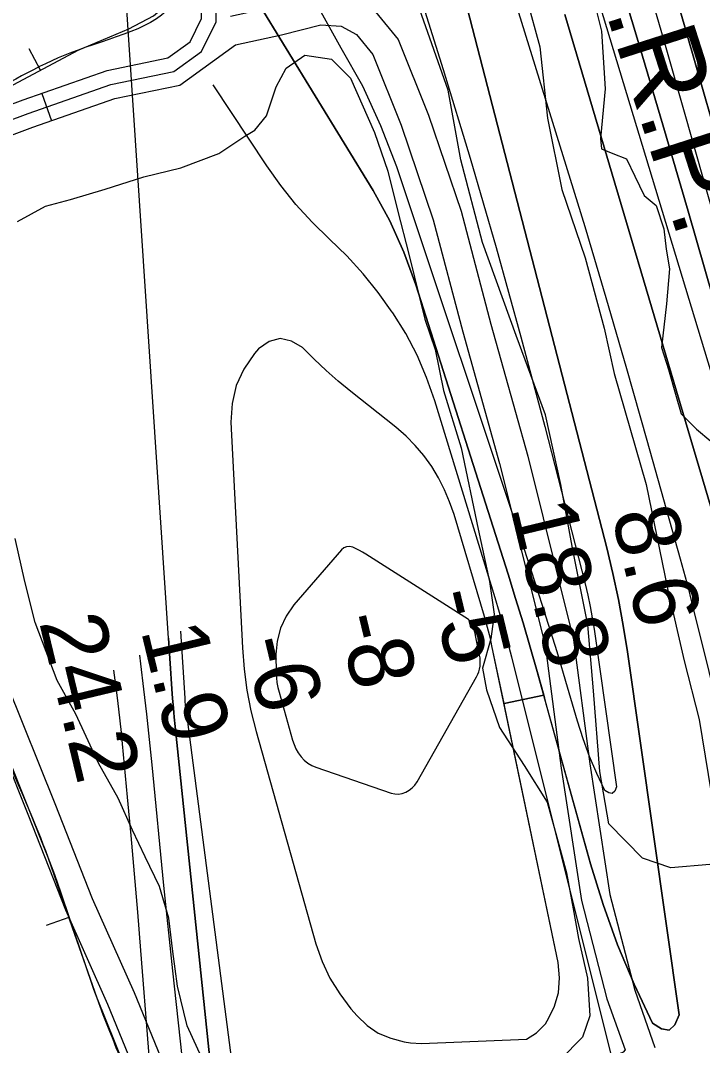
# Model space of a CAD drawing. Extents: x 3625074 to 3663148, y 511451 to 537151.
# Drawn here: x 3631335 to 3632039, y 525814 to 526871 of the extents above; entities that cross this region are included whole.
import ezdxf

# ---------------------------------------------------------------- set-up
doc = ezdxf.new("R2010")
doc.units = 0
for name, color, linetype in [('V-BORW-LINE', 7, 'Continuous'), ('V-RIVR-EDGE', 7, 'Continuous'), ('V-RIVR-RANG', 7, 'Continuous'), ('V-ROAD-CNTR', 7, 'Continuous'), ('V-SITE-VEGE', 7, 'Continuous'), ('V-TOPO-DPTH', 7, 'Continuous'), ('V-TOPO-MINR', 7, 'Continuous'), ('V-TOPO-WATR', 7, 'Continuous'), ('V-TOPO-WATR-IDEN', 7, 'Continuous')]:
    doc.layers.add(name, color=color, linetype=linetype)

msp = doc.modelspace()

# ---------------------------------------------------------------- linework, layer by layer
at = {"layer": 'V-BORW-LINE'}
for p, q in [((3631356.1, 526819.9), (3631344.3, 526841.9)), ((3631385.4, 525946.2), (3631361.8, 525938))]:
    msp.add_line(p, q, dxfattribs=at)
for points in [[(3631302.6, 526791.3), (3631394.9, 526840.7), (3631447.3, 526862.6), (3631472.7, 526875.8), (3631495.6, 526895.8), (3631500.9, 526904.6), (3631502.9, 526912.6), (3631502, 526927.5), (3631488.9, 526973.4), (3631483.9, 527016), (3631478.3, 527058.7), (3631470.8, 527099.7), (3631466.8, 527113.2)], [(3631566.8, 526751.7), (3631577.2, 526758.1), (3631589.1, 526772.9), (3631599.1, 526802.6), (3631609.6, 526822), (3631628.6, 526835.4), (3631656.4, 526831.3), (3631675.7, 526811.6), (3631700.5, 526755.6), (3631714.4, 526715.9), (3631724.3, 526675.6), (3631736.2, 526628.7), (3631752.5, 526563.1), (3631763.2, 526531.8), (3631771.9, 526489.6), (3631790.1, 526430.4), (3631807.4, 526346.5), (3631819.2, 526292.5), (3631824.1, 526258.8), (3631820.6, 526233.5), (3631811.9, 526203.1), (3631816.2, 526181), (3631829.5, 526141.9), (3631855, 526102.8), (3631878.7, 526064.9), (3631888.7, 526029.1), (3631898.7, 525992.1), (3631905.5, 525955), (3631911, 525924.5), (3631920.4, 525883.5), (3631922.6, 525844.6), (3631915.2, 525822.6), (3631892.3, 525799.5)], [(3631332.4, 526663.8), (3631361.1, 526679.7), (3631387.1, 526686.6), (3631422.9, 526697.3), (3631462.6, 526709.9), (3631501, 526719.2), (3631540, 526733.8), (3631566.8, 526751.7)], [(3631441.8, 525795.7), (3631414.5, 525862.8), (3631389.1, 525935.4), (3631364.1, 526008.1), (3631321.4, 526115), (3631278, 526221.5), (3631246.4, 526324.2), (3631214.4, 526427.2), (3631196.1, 526467.4), (3631126.7, 526580.9), (3631116.6, 526597.1), (3631110.5, 526604.2), (3631102.9, 526609.5), (3631096.8, 526611.7), (3631085.7, 526612.6), (3631068.7, 526609.7), (3631052, 526605.2), (3631013.3, 526596.3), (3630975, 526585.1)], [(3631527.6, 525790), (3631507.3, 525834.3), (3631497.3, 525875.3), (3631492.5, 525911), (3631488.3, 525945.4), (3631478.9, 525978), (3631464.2, 526008.6), (3631450.9, 526036), (3631436.3, 526069.2), (3631415.9, 526105.1), (3631392.4, 526155.9), (3631373.2, 526190.5), (3631350.5, 526250.4), (3631339.8, 526292.6), (3631329.9, 526336.9)]]:
    msp.add_lwpolyline(points, dxfattribs=at)
for points in [[(3631461.6, 527110), (3631478.3, 527058.7), (3631488.9, 526973.4), (3631495.6, 526895.8), (3631394.9, 526840.7), (3631210, 526742.4), (3630952, 526645.6), (3630828.4, 526574.9), (3630771.3, 526644.6), (3630731.1, 526688.9), (3630681.2, 526790.4), (3630607.6, 526957.1), (3630583.6, 527107), (3630755.8, 527189), (3630946.7, 527280.8), (3631080.7, 527338.8)], [(3630975, 526585.1), (3631052, 526605.2), (3631102.9, 526609.5), (3631126.7, 526580.9), (3631214.4, 526427.2), (3631278, 526221.5), (3631364.1, 526008.1), (3631414.5, 525862.8), (3631469.9, 525728.9), (3631500, 525646), (3631501, 525593.6), (3631358.1, 525555.8), (3631253.3, 525516), (3631197.2, 525519.2), (3631149.8, 525621.4), (3631070.3, 525800.1), (3631011.3, 525959), (3630940.1, 526137.7), (3630858.5, 526350.5), (3630820.7, 526446.1), (3630877.9, 526518.8), (3630942, 526565.5), (3630975, 526585.1)]]:
    msp.add_spline(points, degree=3, dxfattribs=at)
at = {"layer": 'V-RIVR-EDGE'}
msp.add_lwpolyline([(3631925.1, 526899.1), (3631934.6, 526860.1), (3631938.7, 526800.7), (3631933.7, 526749.6), (3631934.9, 526738.8), (3631946.3, 526734), (3631960.7, 526728.6), (3631969.1, 526710.5), (3631978.6, 526690.7), (3631991.2, 526680.5), (3631998.9, 526656.4), (3632001.3, 526635.4), (3632004.8, 526615), (3632001.7, 526579), (3631996.8, 526534), (3632004, 526511.1), (3632011.1, 526485.9), (3632017.1, 526465.5), (3632032.6, 526449.8), (3632047.6, 526437.2)], dxfattribs=at)
at = {"layer": 'V-ROAD-CNTR'}
msp.add_line((3631357.4, 526796), (3631367.3, 526767.6), dxfattribs=at)
for points in [[(3630816, 526562.2), (3630852.9, 526576.9), (3631064.9, 526672), (3631118.7, 526691), (3631165.4, 526724.2), (3631214.2, 526743.2), (3631338.2, 526789.2), (3631424.8, 526819.5), (3631487.5, 526832.5), (3631510.5, 526849.1), (3631522.2, 526873.3), (3631522, 526911.9), (3631512.6, 526969.7), (3631503.7, 527024.9), (3631476.8, 527089), (3631432.3, 527198.3), (3631386.5, 527303.3), (3631345.3, 527392), (3631339.9, 527430.9), (3631344.3, 527503), (3631470.3, 527554.5), (3631540.1, 527549.8), (3631599.2, 527529.4)], [(3631219.5, 526729.1), (3631343.3, 526775.1), (3631428.8, 526805.1), (3631493.6, 526818.5), (3631522.3, 526839.1), (3631537.2, 526869.9), (3631537, 526913.2), (3631527.4, 526972.2), (3631518.2, 527029), (3631490.6, 527094.8), (3631446.1, 527204.2), (3631400.1, 527309.5), (3631359.8, 527396.3), (3631354.9, 527431.5), (3631358.7, 527492.7), (3631472.8, 527539.3), (3631537.1, 527534.9), (3631594.3, 527515.3)], [(3631552.2, 526875.5), (3631597.7, 526885.5), (3631642.4, 526897), (3631675, 526894.7), (3631701.5, 526880.1), (3631725, 526851.4), (3631756.3, 526773.5), (3631789.9, 526674.4), (3631820.7, 526557.8), (3631858.6, 526421.8), (3631906, 526232.6), (3631922.8, 526104.5), (3631943.4, 525969.7), (3631969, 525871.2), (3631989.9, 525812.1)], [(3631557.3, 526845.9), (3631604.7, 526856.3), (3631645.1, 526866.8), (3631666.3, 526865.3), (3631682, 526856.6), (3631698.9, 526836), (3631728.1, 526763.1), (3631761.2, 526665.7), (3631791.8, 526549.9), (3631829.6, 526414.2), (3631876.5, 526227), (3631893.1, 526100.2), (3631914, 525963.6), (3631940.3, 525862.4), (3631959.1, 525809.5), (3631957.1, 525807.2), (3631893, 525778.3), (3631760.8, 525723.5), (3631659.9, 525686.7), (3631599.1, 525675.4), (3631553.6, 525672.7), (3631537.8, 525673.8)], [(3631133.3, 526664.5), (3631179.8, 526697.6), (3631224.9, 526715.1), (3631348.3, 526761), (3631432.8, 526790.6), (3631499.8, 526804.4), (3631557.3, 526845.9)], [(3631133.3, 526664.5), (3631163.9, 526617), (3631186.3, 526573.3), (3631204.4, 526526.6), (3631229.7, 526446.2), (3631256.1, 526368.3), (3631288.2, 526275.4), (3631321.6, 526186), (3631371, 526063.6), (3631409.5, 525965.6), (3631452.6, 525868.6), (3631486.2, 525787.3), (3631521.7, 525710.5), (3631537.8, 525673.8)], [(3631104.3, 526654.1), (3631137.9, 526602), (3631158.9, 526561), (3631176.1, 526516.6), (3631201.2, 526436.9), (3631227.8, 526358.6), (3631260, 526265.3), (3631293.7, 526175.1), (3631343.1, 526052.5), (3631381.8, 525954), (3631425.1, 525856.8), (3631458.7, 525775.3), (3631494.3, 525698.2), (3631513.5, 525654.5), (3631518.5, 525634.7), (3631523, 525587.2), (3631523.3, 525553.5)]]:
    msp.add_lwpolyline(points, dxfattribs=at)
at = {"layer": 'V-SITE-VEGE'}
for points in [[(3631857.6, 526893.1), (3631871, 526844), (3631879.2, 526770.5), (3631894, 526696.9), (3631917.8, 526626.5), (3631937.5, 526553.7), (3631947.7, 526507), (3631980.8, 526392.5), (3632002.7, 526285.3), (3632019.9, 526210.9), (3632035.6, 526150.3), (3632054.1, 526036.7)], [(3632046.4, 526000.9), (3632006.4, 525997.2), (3631977.1, 526007.3), (3631942.4, 526042.7), (3631933.1, 526096.7), (3631926.6, 526180), (3631920.7, 526247.8), (3631905.1, 526325.4), (3631892.7, 526392.5), (3631877.1, 526464.5), (3631846.8, 526546.4), (3631811.9, 526642.2), (3631789.8, 526727.3), (3631776.7, 526799.2), (3631747.3, 526882)]]:
    msp.add_lwpolyline(points, dxfattribs=at)
at = {"layer": 'V-TOPO-DPTH'}
for points in [[(3631686.1, 527974.3), (3631902.6, 527272.7), (3631906.4, 527260.2), (3631910.3, 527247.6), (3631914.1, 527235.1), (3631917.8, 527222.5), (3631921.5, 527209.9), (3631925.2, 527197.4), (3631928.9, 527184.8), (3631932.5, 527172.2), (3632155.4, 526395.7), (3632165, 526361.9), (3632174.5, 526328), (3632183.8, 526294.1), (3632192.9, 526260.1), (3632201.9, 526226.1), (3632210.7, 526192.1), (3632219.4, 526158), (3632227.9, 526123.9), (3632370.3, 525547.3)], [(3632370.3, 525547.3), (3632227.9, 526123.9), (3632219.4, 526158), (3632210.7, 526192.1), (3632201.9, 526226.1), (3632192.9, 526260.1), (3632183.8, 526294.1), (3632174.5, 526328), (3632165, 526361.9), (3632155.4, 526395.7), (3631932.5, 527172.2), (3631928.9, 527184.8), (3631925.2, 527197.4), (3631921.5, 527209.9), (3631917.8, 527222.5), (3631914.1, 527235.1), (3631910.3, 527247.6), (3631906.4, 527260.2), (3631902.6, 527272.7), (3631686.1, 527974.3)], [(3632269.7, 525753.5), (3632251.1, 525827.5), (3632232.3, 525901.3), (3632133.6, 526285.6), (3632129.6, 526300.9), (3632125.6, 526316.1), (3632121.4, 526331.4), (3632117.2, 526346.6), (3632075.4, 526495.4), (3632050, 526584.9), (3632024.3, 526674.4), (3631998, 526763.7), (3631971.4, 526852.9), (3631867, 527199.3), (3631861.3, 527217.9), (3631855.5, 527236.6), (3631849.5, 527255.1), (3631843.4, 527273.7), (3631812.1, 527368.1), (3631789.8, 527433.6), (3631766.6, 527498.9), (3631742.3, 527563.7), (3631717.2, 527628.2), (3631629.3, 527848.4)], [(3631629.3, 527848.4), (3631717.2, 527628.2), (3631742.3, 527563.7), (3631766.6, 527498.9), (3631789.8, 527433.6), (3631812.1, 527368.1), (3631843.4, 527273.7), (3631849.5, 527255.1), (3631855.5, 527236.6), (3631861.3, 527217.9), (3631867, 527199.3), (3631971.4, 526852.9), (3631998, 526763.7), (3632024.3, 526674.4), (3632050, 526584.9), (3632075.4, 526495.4), (3632117.2, 526346.6), (3632121.4, 526331.4), (3632125.6, 526316.1), (3632129.6, 526300.9), (3632133.6, 526285.6), (3632232.3, 525901.3), (3632251.1, 525827.5), (3632269.7, 525753.5)], [(3631744.3, 524499.3), (3631738.3, 524531.6), (3631606, 525245.3), (3631603.2, 525260.9), (3631600.5, 525276.6), (3631597.9, 525292.2), (3631595.5, 525307.9), (3631576.1, 525437.6), (3631564.5, 525518.2), (3631553.7, 525598.9), (3631544, 525679.7), (3631535, 525760.6), (3631495, 526142.9), (3631494, 526152.6), (3631493.2, 526162.4), (3631492.4, 526172.1), (3631491.7, 526181.9), (3631488.1, 526234.2), (3631428.4, 527136.9)], [(3631428.4, 527136.9), (3631428.6, 527136.8), (3631429.4, 527136.1), (3631429.9, 527135.3), (3631699.3, 526695.9), (3631716.5, 526664.7), (3631730.8, 526632.2), (3631743.2, 526598.6), (3631838.4, 526300), (3631846.2, 526275.1), (3631853.9, 526250), (3631861.2, 526225), (3631868.3, 526199.8), (3631875.2, 526175.3), (3631834.2, 526166.9)], [(3631835.4, 526161.2), (3631834.2, 526166.9), (3631875.2, 526175.3), (3631876.8, 526169.2), (3631923.5, 526001.6), (3631936.6, 525959.4), (3631951.3, 525917.8), (3631968.5, 525877.2), (3631987.3, 525837.2), (3631996.7, 525831.2), (3632004.7, 525829.8), (3632010.5, 525835.5), (3632014.8, 525845.9), (3631961.5, 526220.2), (3631957.2, 526247.2), (3631952.3, 526274.1), (3631946.5, 526300.8), (3631940.1, 526327.3), (3631753, 527052)], [(3632263, 525506.3), (3632150.9, 525977.4), (3632137.7, 526031.7), (3632124.3, 526085.9), (3632110.4, 526140), (3632096.3, 526194.1), (3632085.9, 526232.8), (3632076.6, 526267.3), (3632067, 526301.9), (3632057.2, 526336.3), (3632047.1, 526370.7), (3631896.9, 526877.4)], [(3631896.9, 526877.4), (3632047.1, 526370.7), (3632057.2, 526336.3), (3632067, 526301.9), (3632076.6, 526267.3), (3632085.9, 526232.8), (3632096.3, 526194.1), (3632110.4, 526140), (3632124.3, 526085.9), (3632137.7, 526031.7), (3632150.9, 525977.4), (3632263, 525506.3)], [(3631654.6, 525883.5), (3631664.7, 525867.3), (3631676.3, 525851.8), (3631682.6, 525844.6), (3631693, 525834.9), (3631704.4, 525826.9), (3631717.3, 525821.6), (3631731.1, 525818), (3631737.9, 525817), (3631749.1, 525816.1), (3631857.5, 525820.6), (3631867.7, 525827.1), (3631876.9, 525836.5), (3631878.8, 525839.6), (3631885.8, 525853.8), (3631890.3, 525868.5), (3631891.4, 525883.8), (3631890, 525899.6), (3631821.8, 526226.3), (3631820.1, 526233.9), (3631818.3, 526241.4), (3631816.3, 526248.9), (3631814.2, 526256.4), (3631782.7, 526361.7), (3631778.1, 526374.7), (3631772.9, 526387.3), (3631766.6, 526399.5), (3631759.6, 526411.3), (3631751.5, 526422.4), (3631742.7, 526433), (3631733.1, 526442.6), (3631722.7, 526451.7), (3631676.3, 526488.4), (3631663.3, 526499.2), (3631650.6, 526510.3), (3631638.3, 526521.9), (3631626.4, 526533.9), (3631614.9, 526540.6), (3631603.4, 526543.3), (3631592.1, 526540), (3631581, 526532.6), (3631576.7, 526527.7), (3631565.9, 526511.6), (3631557.8, 526494.6), (3631553.8, 526476.1), (3631552.5, 526456.8), (3631564.3, 526224.1), (3631566.1, 526202.3), (3631568.9, 526180.6), (3631573.2, 526159.2), (3631578.4, 526137.9), (3631640.2, 525919.1), (3631646.7, 525900.9), (3631654.6, 525883.5)], [(3631834.2, 526166.9), (3631821.8, 526226.3), (3631820.1, 526233.9), (3631818.3, 526241.4), (3631816.3, 526248.9), (3631814.2, 526256.4), (3631782.7, 526361.7), (3631778.1, 526374.7), (3631772.9, 526387.3), (3631766.6, 526399.5), (3631759.6, 526411.3), (3631751.5, 526422.4), (3631742.7, 526433), (3631733.1, 526442.6), (3631722.7, 526451.7), (3631676.3, 526488.4), (3631663.3, 526499.2), (3631650.6, 526510.3), (3631638.3, 526521.9), (3631626.4, 526533.9), (3631614.9, 526540.6), (3631603.4, 526543.3), (3631592.1, 526540), (3631581, 526532.6), (3631576.7, 526527.7), (3631565.9, 526511.6), (3631557.8, 526494.6), (3631553.8, 526476.1), (3631552.5, 526456.8), (3631564.3, 526224.1), (3631566.1, 526202.3), (3631568.9, 526180.6), (3631573.2, 526159.2), (3631578.4, 526137.9), (3631640.2, 525919.1), (3631646.7, 525900.9), (3631654.6, 525883.5)], [(3631654.6, 525883.5), (3631664.7, 525867.3), (3631676.3, 525851.8), (3631682.6, 525844.6), (3631693, 525834.9), (3631704.4, 525826.9), (3631717.3, 525821.6), (3631731.1, 525818), (3631737.9, 525817), (3631749.1, 525816.1), (3631857.5, 525820.6), (3631867.7, 525827.1), (3631876.9, 525836.5), (3631878.8, 525839.6), (3631885.8, 525853.8), (3631890.3, 525868.5), (3631891.4, 525883.8), (3631890, 525899.6), (3631835.4, 526161.2)]]:
    msp.add_lwpolyline(points, dxfattribs=at)
at = {"layer": 'V-TOPO-MINR'}
for points in [[(3631686.1, 527974.3), (3631902.6, 527272.7), (3631906.4, 527260.2), (3631910.3, 527247.6), (3631914.1, 527235.1), (3631917.8, 527222.5), (3631921.5, 527209.9), (3631925.2, 527197.4), (3631928.9, 527184.8), (3631932.5, 527172.2), (3632155.4, 526395.7), (3632165, 526361.9), (3632174.5, 526328), (3632183.8, 526294.1), (3632192.9, 526260.1), (3632201.9, 526226.1), (3632210.7, 526192.1), (3632219.4, 526158), (3632227.9, 526123.9), (3632370.3, 525547.3)], [(3631629.3, 527848.4), (3631717.2, 527628.2), (3631742.3, 527563.7), (3631766.6, 527498.9), (3631789.8, 527433.6), (3631812.1, 527368.1), (3631843.4, 527273.7), (3631849.5, 527255.1), (3631855.5, 527236.6), (3631861.3, 527217.9), (3631867, 527199.3), (3631971.4, 526852.9), (3631998, 526763.7), (3632024.3, 526674.4), (3632050, 526584.9), (3632075.4, 526495.4), (3632117.2, 526346.6), (3632121.4, 526331.4), (3632125.6, 526316.1), (3632129.6, 526300.9), (3632133.6, 526285.6), (3632232.3, 525901.3), (3632251.1, 525827.5), (3632269.7, 525753.5)], [(3631698.5, 527797), (3631727.4, 527716), (3631755.3, 527634.7), (3631782.3, 527553.1), (3631862.4, 527305.7), (3631872.6, 527273.9), (3631882.6, 527242), (3631892.5, 527210.1), (3631902.2, 527178.1), (3631929.6, 527086.5), (3631952.7, 527008.7), (3631975.6, 526930.8), (3631998.2, 526852.8), (3632020.6, 526774.7), (3632134, 526375.6), (3632141.5, 526348.7), (3632149, 526321.8), (3632156.2, 526294.9), (3632163.4, 526267.9), (3632194.9, 526147.6), (3632217.5, 526060.4), (3632239.8, 525973.1), (3632261.7, 525885.7), (3632283.2, 525798.2)], [(3631831.9, 527220.3), (3632054.8, 526485.1), (3632063.5, 526456.2), (3632072, 526427.2), (3632080.3, 526398.2), (3632088.4, 526369.2), (3632101.9, 526320.5), (3632103.2, 526315.7), (3632104.5, 526311), (3632105.7, 526306.3), (3632106.9, 526301.5), (3632289.7, 525573.9)], [(3631753.2, 527189.1), (3631895, 526732), (3631917.4, 526658.8), (3631939.3, 526585.5), (3631960.7, 526512.1), (3631981.6, 526438.5), (3632015.9, 526315.9), (3632019.3, 526303.5), (3632022.7, 526291.1), (3632025.9, 526278.7), (3632029.1, 526266.2), (3632160.3, 525738.3)], [(3631663.5, 527164.5), (3631771.4, 526820.6), (3631799.3, 526729.1), (3631826.2, 526637.2), (3631851.7, 526545), (3631876.2, 526452.5), (3631917.9, 526290.1), (3631920.6, 526278.5), (3631923.1, 526266.9), (3631925.2, 526255.3), (3631927.1, 526243.6), (3631950.3, 526080.9), (3631948.4, 526076.4), (3631945.9, 526074), (3631942.4, 526074.5), (3631938.3, 526077.2), (3631930.1, 526094.5), (3631922.5, 526112.1), (3631916, 526130.2), (3631910.1, 526148.4), (3631899.7, 526183.8), (3631888.9, 526219.9), (3631877.8, 526255.9), (3631866.4, 526291.7), (3631854.7, 526327.5), (3631723.5, 526720.3), (3631707.2, 526762.5), (3631688.5, 526803.5), (3631666.2, 526842.6), (3631497, 527147.3)], [(3631753, 527052), (3631940.1, 526327.3), (3631946.5, 526300.8), (3631952.3, 526274.1), (3631957.2, 526247.2), (3631961.5, 526220.2), (3632014.8, 525845.9), (3632010.5, 525835.5), (3632004.7, 525829.8), (3631996.7, 525831.2), (3631987.3, 525837.2), (3631968.5, 525877.2), (3631951.3, 525917.8), (3631936.6, 525959.4), (3631923.5, 526001.6), (3631868.3, 526199.8), (3631861.2, 526225), (3631853.9, 526250), (3631846.2, 526275.1), (3631838.4, 526300), (3631743.2, 526598.6), (3631730.8, 526632.2), (3631716.5, 526664.7), (3631699.3, 526695.9), (3631429.9, 527135.3)], [(3631949.1, 525787.3), (3631842.2, 526214.5), (3631838.2, 526229.9), (3631834, 526245.2), (3631829.6, 526260.5), (3631825.1, 526275.8), (3631762.9, 526479), (3631754.4, 526502.8), (3631744.6, 526526), (3631732.8, 526548.2), (3631719.5, 526569.8), (3631719, 526570.5), (3631704.4, 526590.7), (3631688.8, 526610), (3631671.9, 526628.3), (3631654.1, 526645.7), (3631636.4, 526663.2), (3631619.6, 526681.5), (3631604.1, 526700.9), (3631589.6, 526721.2), (3631534.3, 526804.8)], [(3631619.6, 526120), (3631622, 526115.9), (3631624.8, 526111.9), (3631628.1, 526108.5), (3631631.7, 526105.4), (3631635.8, 526103), (3631640.1, 526101.1), (3631717.8, 526074.4), (3631721.6, 526073.5), (3631725.5, 526073.3), (3631729.2, 526074), (3631733, 526075.3), (3631736.4, 526077.3), (3631739.5, 526079.8), (3631742.2, 526082.7), (3631744.5, 526086), (3631805.8, 526194.3), (3631807.1, 526196.9), (3631808.2, 526199.6), (3631808.9, 526202.3), (3631809.5, 526205.2), (3631809.7, 526208.1), (3631809.7, 526211), (3631809.5, 526213.9), (3631809, 526216.8), (3631804.8, 526237), (3631804.7, 526237.5), (3631804.4, 526238.6), (3631804.3, 526239.2), (3631802, 526246.7), (3631800.8, 526249.6), (3631798.2, 526252.8), (3631797.4, 526253.4), (3631691.5, 526320.8), (3631688.3, 526322.8), (3631685, 526324.6), (3631681.6, 526326.3), (3631678.2, 526327.9), (3631674.9, 526328.6), (3631671.8, 526328.5), (3631669, 526327.2), (3631666.4, 526325.2), (3631617.5, 526268.4), (3631609.5, 526256.8), (3631603.5, 526244.5), (3631600.3, 526231.2), (3631598.9, 526217.3), (3631599.2, 526198.3), (3631599.5, 526193.3), (3631600, 526188.3), (3631600.9, 526183.4), (3631602.1, 526178.5), (3631616.1, 526129), (3631617.7, 526124.4), (3631619.6, 526120)], [(3631500.4, 526241.3), (3631504.8, 526172.2), (3631505.1, 526168.8), (3631505.4, 526165.3)], [(3631488.1, 526234.2), (3631491.7, 526181.9), (3631492.4, 526172.1), (3631493.2, 526162.4), (3631494, 526152.6), (3631495, 526142.9), (3631535, 525760.6), (3631544, 525679.7), (3631553.7, 525598.9), (3631564.5, 525518.2), (3631576.1, 525437.6), (3631595.5, 525307.9), (3631597.9, 525292.2), (3631600.5, 525276.6), (3631603.2, 525260.9), (3631606, 525245.3), (3631738.3, 524531.6), (3631744.3, 524499.3)], [(3631458.2, 526216.7), (3631459.3, 526207.6), (3631462.4, 526181.7), (3631465.4, 526155.7), (3631468.2, 526129.6), (3631470.8, 526103.6), (3631483.1, 525979.2), (3631492.2, 525891), (3631501.9, 525802.9)], [(3631431.5, 526201.2), (3631435.1, 526172.8), (3631436.6, 526160.9), (3631438, 526149), (3631439.2, 526137), (3631440.4, 526125.1), (3631445.6, 526070.1), (3631449.3, 526030.6), (3631452.8, 525991.1), (3631456.1, 525951.6), (3631459.3, 525912.1), (3631474.9, 525712.8), (3631471.7, 525704.3), (3631467, 525699)], [(3631505.4, 526165.3), (3631505.7, 526161.9), (3631506.2, 526158.5), (3631601.9, 525422.8)]]:
    msp.add_lwpolyline(points, dxfattribs=at)
at = {"layer": 'V-TOPO-WATR'}
for points in [[(3631896.9, 526877.4), (3632047.1, 526370.7), (3632057.2, 526336.3), (3632067, 526301.9), (3632076.6, 526267.3), (3632085.9, 526232.8), (3632096.3, 526194.1), (3632110.4, 526140), (3632124.3, 526085.9), (3632137.7, 526031.7), (3632150.9, 525977.4), (3632263, 525506.3)], [(3631654.6, 525883.5), (3631664.7, 525867.3), (3631676.3, 525851.8), (3631682.6, 525844.6), (3631693, 525834.9), (3631704.4, 525826.9), (3631717.3, 525821.6), (3631731.1, 525818), (3631737.9, 525817), (3631749.1, 525816.1), (3631857.5, 525820.6), (3631867.7, 525827.1), (3631876.9, 525836.5), (3631878.8, 525839.6), (3631885.8, 525853.8), (3631890.3, 525868.5), (3631891.4, 525883.8), (3631890, 525899.6), (3631821.8, 526226.3), (3631820.1, 526233.9), (3631818.3, 526241.4), (3631816.3, 526248.9), (3631814.2, 526256.4), (3631782.7, 526361.7), (3631778.1, 526374.7), (3631772.9, 526387.3), (3631766.6, 526399.5), (3631759.6, 526411.3), (3631751.5, 526422.4), (3631742.7, 526433), (3631733.1, 526442.6), (3631722.7, 526451.7), (3631676.3, 526488.4), (3631663.3, 526499.2), (3631650.6, 526510.3), (3631638.3, 526521.9), (3631626.4, 526533.9), (3631614.9, 526540.6), (3631603.4, 526543.3), (3631592.1, 526540), (3631581, 526532.6), (3631576.7, 526527.7), (3631565.9, 526511.6), (3631557.8, 526494.6), (3631553.8, 526476.1), (3631552.5, 526456.8), (3631564.3, 526224.1), (3631566.1, 526202.3), (3631568.9, 526180.6), (3631573.2, 526159.2), (3631578.4, 526137.9), (3631640.2, 525919.1), (3631646.7, 525900.9), (3631654.6, 525883.5)]]:
    msp.add_lwpolyline(points, dxfattribs=at)

# ---------------------------------------------------------------- texts
at = {"layer": 'V-RIVR-RANG'}
for s, p in [('18.8', (3631840.3, 526369)), ('8.6', (3631944.8, 526362.1)), ('-5', (3631759, 526279.5)), ('24.2', (3631354.5, 526250.9)), ('-8', (3631662.1, 526254.8)), ('1.9', (3631459.4, 526242.5)), ('-6', (3631565.1, 526230.7))]:
    msp.add_text(s, height=67, rotation=283.5283, dxfattribs=at).set_placement(p)
at = {"layer": 'V-TOPO-WATR-IDEN'}
msp.add_text('L.W.R.P.', height=83, rotation=287.7902, dxfattribs=at).set_placement((3631878.8, 527067.3))

doc.saveas('drawing.dxf')
